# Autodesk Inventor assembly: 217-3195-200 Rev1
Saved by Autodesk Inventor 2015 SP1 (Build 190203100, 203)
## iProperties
Created: 2014-11
Part Number: 217-3195-200 Rev1
Document SubType Name: Assembly
Designer: User
Author: User
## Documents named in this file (4)
- C:\Users\User\Documents\6 CIM Gearbox Pack and Go\217-3195-200 Rev1.iam
- C:\Users\User\Documents\6 CIM Gearbox Pack and Go\217-3195-010 Rev1.ipt
- C:\Users\User\Documents\6 CIM Gearbox Pack and Go\217-2778-NCQ8A075-050M_1032_Nut_90545A111.ipt
- C:\Users\User\Documents\6 CIM Gearbox Pack and Go\91251A107_91251A107.ipt
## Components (5 placed, 5 different names)
1. 217-3195-010 Rev1_104
2. 217-3195-010 Rev1_105
3. 217-2778-NCQ8A075-050M_1032_Nut_90545A111_106
4. 91251A107_91251A107_107
5. 91251A107_91251A107_108
